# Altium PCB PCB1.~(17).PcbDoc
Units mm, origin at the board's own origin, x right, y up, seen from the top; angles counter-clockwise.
Board outline 145.29 x 144.91 mm, 2 copper layers (Top Layer, Bottom Layer); 48 components, 44 nets, 249 pads, 0 vias.
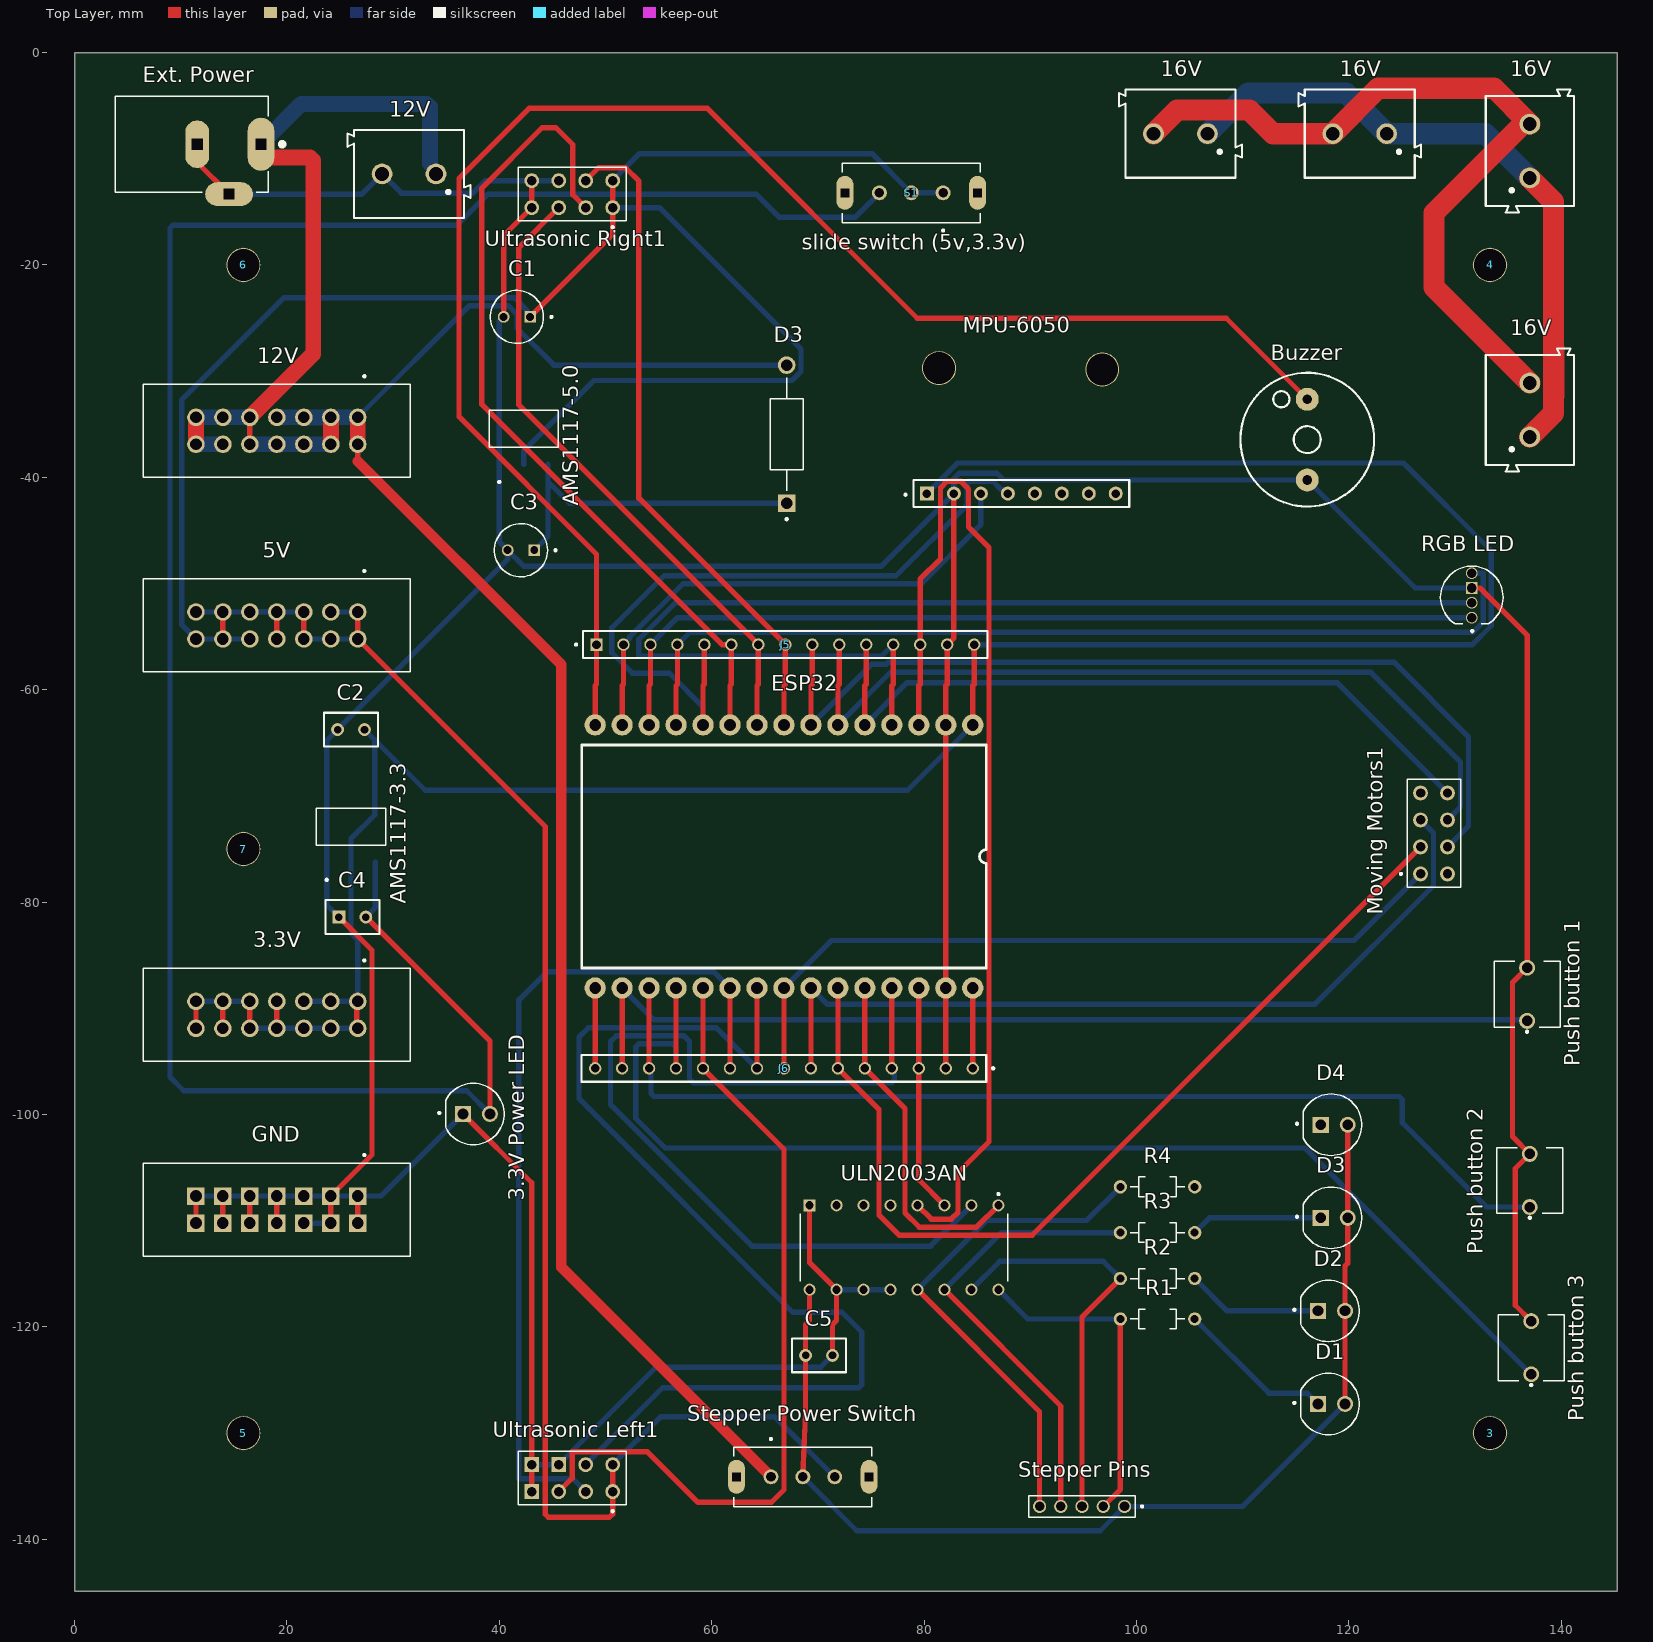
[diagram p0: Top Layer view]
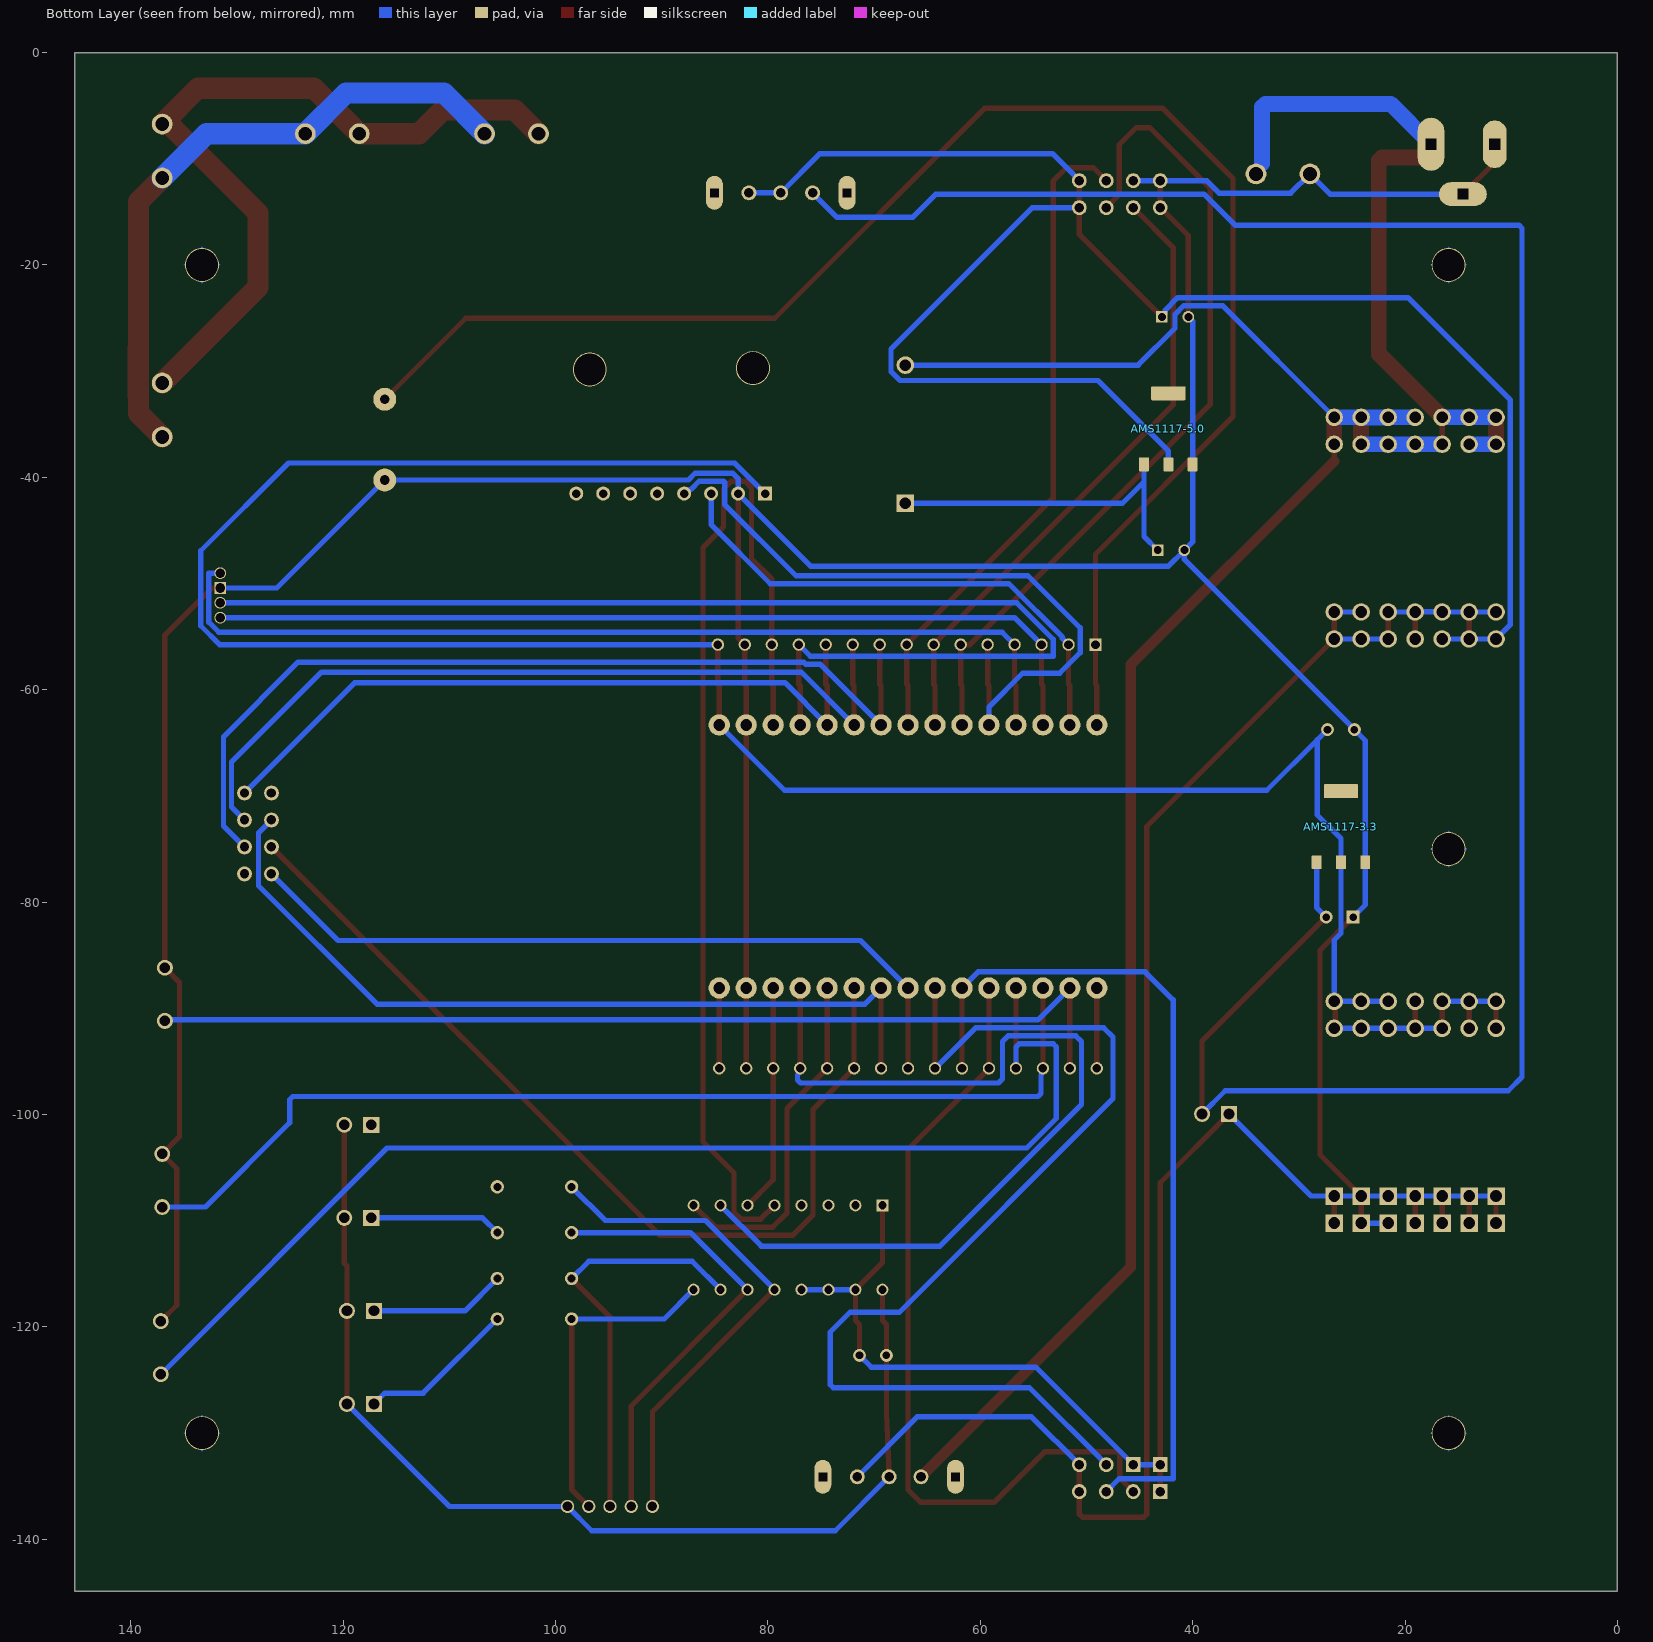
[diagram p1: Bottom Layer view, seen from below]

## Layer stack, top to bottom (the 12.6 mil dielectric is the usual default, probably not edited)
Top Solder: solder mask 0.0102, Solder Resist, Dk 3.5
Top Layer: signal copper 0.0356
Dielectric 1: dielectric 0.32, FR-4, Dk 4.8
Bottom Layer: signal copper 0.0356
Bottom Solder: solder mask 0.0102, Solder Resist, Dk 3.5

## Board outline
0,-144.907 145.288,-144.907 145.288,0 0,0

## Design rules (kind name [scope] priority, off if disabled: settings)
Clearance [All] p1: gap=0.254 ignorepadtopadclearanceinfootprint=FALSE except(0: Arc-Hole Track-Hole SMDPad-Hole THPad-Hole Via-Hole Fill-Hole Poly-Hole Region-Hole Text-Hole; 2: Arc-Poly Track-Poly SMDPad-Poly THPad-Poly)
PolygonConnect [All] p1: connectstyle=Relief reliefconductorwidth=0.254 reliefentries=4 polygonreliefangle="90 Angle" airgapwidth=0.254
RoutingVias [All] p1: holewidth=0.711 width=1.27 viastyle="Through Hole" minholewidth=0.711 minwidth=1.27 maxholewidth=0.711 maxwidth=1.27
SolderMaskExpansion [All] p1: expansion=0.102 istentingtop=FALSE
Width [All] p1: maxlimit=3 minlimit=0.254 preferedwidth=2
30 further rules are at their usual default settings.

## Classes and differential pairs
component class Sheet1: 3 3.3V "3.3V Power LED" 4 5 5V 6 7 12V 16V AMS1117-3.3 AMS1117-5.0 Buzzer C1 C2 C3 C4 C5 D1 D2 D3 ESP32 "Ext. Power" GND J5 J6 "Moving motors" "Moving Motors1" MPU-6050 "Push button 1" "Push button 2" "Push button 3" R1 R2 R3 R4 "RGB LED" S1 "Stepper Pins" "Stepper Power Switch" ULN2003AN "Ultrasonic Left1" "Ultrasonic Right1"

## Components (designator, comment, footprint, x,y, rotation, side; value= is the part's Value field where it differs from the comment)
3 "Mounting Hole" PCBComponent_1 133.288,-130 r90 top
3.3V "3.3v pin headers block" AMPHENOL_52601-S14-4LF#1 19.05,-90.616 r180 top
"3.3V Power LED" "LED 5mm" "LED 5mm" 37.846,-99.949 r0 top
4 "Mounting Hole" PCBComponent_1 133.288,-20 r90 top
5 "Mounting Hole" PCBComponent_1 15.9,-130 r90 top
5V "5v pin headers block" AMPHENOL_52601-S14-4LF#1 19.05,-53.949 r180 top
6 "Mounting Hole" PCBComponent_1 15.9,-20 r90 top
7 "Mounting Hole" PCBComponent_1 15.9,-75 r90 top
12V "12v pin headers block" AMPHENOL_52601-S14-4LF#1 19.05,-35.616 r180 top
12V "From Buck" 691213510002 31.496,-11.43 r180 top
16V "From Buck" 691213510002 137.033,-9.271 r90 top
16V "From Buck" 691213510002 137.033,-33.655 r90 top
16V "From Buck" 691213510002 121.02,-7.641 r180 top
16V "From Buck" 691213510002 104.14,-7.641 r180 top
AMS1117-3.3 "AMS1117-3.3" SOT229P700X180-4N 26.035,-72.898 r90 top
AMS1117-5.0 "AMS1117-5.0" SOT229P700X180-4N 42.291,-35.433 r90 top
Buzzer "WST-1205S" WST-1205S 116.078,-36.449 r90 top
C1 "CAP  33UF 50V RADIAL" "CAP  33UF 50V RADIAL" 41.656,-24.892 r180 top
C2 "Ceramic Capacitor 100nF" C320C#1 33.035,-56.754 r0 top
C3 "CAP  33UF 50V RADIAL" "CAP  33UF 50V RADIAL" 42.037,-46.863 r180 top
C4 "Ceramic Capacitor 100nF" C320C#2 33.162,-74.407 r0 top
C5 "Ceramic Capacitor 100nF" C320C#1 63.104,-129.682 r180 top
D1 "LED 5mm" "LED 5mm" 118.364,-127.254 r0 top
D2 "LED 5mm" "LED 5mm" 118.364,-118.491 r0 top
D3 "LED 5mm" "LED 5mm" 118.618,-109.728 r0 top
D3 "RL207" DIOAD1300W80L670D310 67.056,-35.941 r90 top
D4 "LED 5mm" "LED 5mm" 118.618,-100.965 r0 top
ESP32 "ESP32DEVKITV1" ESP32DEVKITV1 66.929,-75 r90 top
"Ext. Power" "DC Power Jack Female Socket" "DC Power Jack Female Socket" 17.557,-8.636 r180 top
GND "GND pin headers block" AMPHENOL_52601-S14-4LF#2 19.05,-108.949 r180 top
J5 "TS-115-T-A-1" SAMTEC_TS-115-T-A-1#1 66.929,-55.753 r0 top
J6 "TS-115-T-A-1" SAMTEC_TS-115-T-A-1#2 66.802,-95.649 r180 top
"Moving Motors1" "Pin header female block 8 pin" "Pin header female block 8 pin"#1 128.016,-73.533 r90 top (schematic designator "Moving motors1")
MPU-6050 "MPU-6050" MPU-6050 78.74,-43.053 r90 top
"Push button 1" "FSM8JRT" TE_FSM8JRT 136.779,-91.186 r90 top
"Push button 2" "FSM8JRT" TE_FSM8JRT 137.033,-108.712 r90 top
"Push button 3" "FSM8JRT" TE_FSM8JRT 137.16,-124.46 r90 top
R1 "Resistor" RESAD700W45L350D185 101.981,-119.253 r180 top
R2 "Resistor" RESAD700W45L350D185 101.981,-115.443 r180 top
R3 "Resistor" RESAD700W45L350D185 101.981,-111.125 r180 top
R4 "Resistor" RESAD700W45L350D185 101.981,-106.807 r180 top
"RGB LED" "common cathode" "LED RGB 5mm" 131.572,-51.308 r90 top
S1 "slide switch (5v,3.3v)" "Slide switch" 78.788,-13.208 r180 top
"Stepper Pins" "Pin hreader 5 pins" "Pin hreader 5 pins" 98.869,-136.906 r180 top
"Stepper Power Switch" "Slide switch" "Slide switch" 68.58,-134.112 r0 top
ULN2003AN "ULN2003AN" DIP794W45P254L1969H508Q16 78.105,-112.522 r270 top
"Ultrasonic Left1" "Pin header female block 8 pin" "Pin header female block 8 pin"#2 46.863,-134.239 r180 top
"Ultrasonic Right1" "Pin header female block 8 pin" "Pin header female block 8 pin"#1 46.863,-13.335 r180 top

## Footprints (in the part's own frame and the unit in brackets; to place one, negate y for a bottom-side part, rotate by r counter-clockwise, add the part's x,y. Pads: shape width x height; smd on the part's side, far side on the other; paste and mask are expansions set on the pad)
691213510002 [mm]
  round 1.95 hole 1.3: 1(-2.54,0) 2(2.54,0)
  silkscreen extent -5.78,-4.15 5.78,4.15, body extent -5.68,-3.94 5.68,4.16, height 10
AMPHENOL_52601-S14-4LF#1 [mm]
  round 1.65 hole 1.1: 1(-7.62,-1.27) 2(-7.62,1.27) 3(-5.08,-1.27) 4(-5.08,1.27) 5(-2.54,-1.27) 6(-2.54,1.27) 7(0,-1.27) 8(0,1.27) 9(2.54,-1.27) 10(2.54,1.27) 11(5.08,-1.27) 12(5.08,1.27) 13(7.62,-1.27) 14(7.62,1.27)
  silkscreen extent -12.57,-5.23 12.57,4.38, body extent -12.57,-4.38 12.57,4.38, height 9.53
AMPHENOL_52601-S14-4LF#2 [mm]
  rect 1.65x1.65 hole 1.1: 1(-7.62,-1.27) 2(-7.62,1.27) 3(-5.08,-1.27) 4(-5.08,1.27) 5(-2.54,-1.27) 6(-2.54,1.27) 7(0,-1.27) 8(0,1.27) 9(2.54,-1.27) 10(2.54,1.27) 11(5.08,-1.27) 12(5.08,1.27) 13(7.62,-1.27) 14(7.62,1.27)
  silkscreen extent -12.57,-5.23 12.57,4.38, body extent -12.57,-4.38 12.57,4.38, height 9.53
C320C#1 [mm]
  round 1.21 hole 0.71: 1(-8.27,-7) 2(-5.73,-7)
  silkscreen extent -9.54,-8.59 -4.46,-5.41, body extent -9.53,-8.57 -4.45,-5.4, height 7.1
C320C#2 [mm]
  rect 1.21x1.21 hole 0.71: 1(-8.27,-7)
  round 1.21 hole 0.71: 2(-5.73,-7)
  silkscreen extent -9.54,-8.59 -4.46,-5.41, body extent -9.53,-8.57 -4.45,-5.4, height 7.1
"CAP  33UF 50V RADIAL" [mm]
  round 1.1 hole 0.75: N(1.25,0)
  rect 1.1x1.1 hole 0.75: P(-1.25,0)
  silkscreen extent -3.35,-2.5 2.5,2.5, body extent -2.49,-2.5 2.5,2.5, height 11
"DC Power Jack Female Socket" [mm]
  oval 2.5x5 hole 1 square: 1(0,0)
  oval 2.25x4.5 hole 1 square: 2(6,0)
  oval 4.5x2.25 hole 1 square: 3(3,4.7)
  silkscreen extent -2.2,-4.5 13.7,4.5, body extent -0.7,-4.5 13.7,4.9, height 11
DIOAD1300W80L670D310 [mm]
  round 1.65 hole 1.1: A(6.5,0)
  rect 1.65x1.65 hole 1.1: C(-6.5,0)
  silkscreen extent -8.1,-1.55 5.32,1.55, body extent -6.9,-1.95 6.9,1.65, height 3.6
DIP794W45P254L1969H508Q16 [mm]
  round 1.13 hole 0.78: 1(-3.97,8.89) 2(-3.97,6.35) 3(-3.97,3.81) 4(-3.97,1.27) 5(-3.97,-1.27) 6(-3.97,-3.81) 7(-3.97,-6.35) 9(3.97,-8.89) 10(3.97,-6.35) 11(3.97,-3.81) 12(3.97,-1.27) 13(3.97,1.27) 14(3.97,3.81) 15(3.97,6.35) 16(3.97,8.89)
  rect 1.13x1.13 hole 0.78: 8(-3.97,-8.89)
  silkscreen extent -5.13,-9.77 3.18,9.77, body extent -3.95,-10.54 3.95,10.8, height 5.08
ESP32DEVKITV1 [mm]
  round 2 hole 1.1: 1(11.684,-17.653) 2(11.684,-15.113) 3(11.684,-12.573) 4(11.684,-10.033) 5(11.684,-7.493) 6(11.684,-4.953) 7(11.684,-2.413) 8(11.684,0.127) 9(11.684,2.667) 10(11.684,5.207) 11(11.684,7.747) 12(11.684,10.287) 13(11.684,12.827) 14(11.684,15.367) 15(11.684,17.907) 16(-13.086,17.907) 17(-13.086,15.367) 18(-13.086,12.827) 19(-13.086,10.287) 20(-13.086,7.747) 21(-13.086,5.207) 22(-13.086,2.667) 23(-13.086,0.127) 24(-13.086,-2.413) 25(-13.086,-4.953) 26(-13.086,-7.493) 27(-13.086,-10.033) 28(-13.086,-12.573) 29(-13.086,-15.113) 30(-13.086,-17.653)
  silkscreen extent -11.2,-18.92 9.79,19.18, body extent -15.13,-28.49 13.86,24.48, height 8.36
"LED 5mm" [mm]
  round 1.508 hole 1: A(1.27,0)
  rect 1.508x1.508 hole 1: C(-1.27,0)
  silkscreen extent -3.6,-2.9 2.6,2.9, body extent -2.88,-2.9 2.51,2.9, height 12.1
"LED RGB 5mm" [mm]
  round 1.1 hole 0.9: 1(-1.905,0) 2(-0.508,0) 4(2.286,0)
  rect 1.1x1.1 hole 0.9: 3(0.889,0)
  silkscreen extent -3.27,-2.95 2.95,2.95, body extent -2.47,-3.05 2.98,2.84, height 9.6
MPU-6050 [mil]
  rect 52x52 hole 32: 01(60,-60)
  round 52 hole 32: 02(60,-160) 03(60,-260) 04(60,-360) 05(60,-460) 06(60,-560) 07(60,-660) 08(60,-760)
  round 125.98 hole 118.11: ""(520,-710) ""(525,-105)
  silkscreen extent 10,-810 110,23, body extent 15,-811 615,-9, height 612
PCBComponent_1 [mm]
  round 3.2 hole 3: ""(0,0)
  Bottom Layer lines w0.15: 0,1.649 0,-1.651 ; -1.651,0 1.649,0
"Pin header female block 8 pin"#1 [mm]
  round 1.398 hole 0.89: 1(-3.81,1.27) 2(-1.27,1.27) 3(1.27,1.27) 4(3.81,1.27) 5(-3.81,-1.27) 6(-1.27,-1.27) 7(1.27,-1.27) 8(3.81,-1.27)
  silkscreen extent -5.08,-2.52 5.08,3.21, body extent -5.08,-2.51 5.08,2.51, height 6.22
"Pin header female block 8 pin"#2 [mm]
  round 1.398 hole 0.89: 1(-3.81,1.27) 2(-1.27,1.27) 3(1.27,1.27) 5(-3.81,-1.27) 6(-1.27,-1.27)
  rect 1.398x1.398 hole 0.89: 4(3.81,1.27) 7(1.27,-1.27) 8(3.81,-1.27)
  silkscreen extent -5.08,-2.52 5.08,3.21, body extent -5.08,-2.51 5.08,2.51, height 6.22
"Pin hreader 5 pins" [mm]
  round 1.25 hole 0.9: 1(0,0) 2(2,0) 3(4,0) 4(6,0) 5(8,0)
  silkscreen extent -1.75,-1 9,1, body extent -1,-1 9,1, height 5.65
RESAD700W45L350D185 [mm]
  round 1.258 hole 0.75: 1(-3.5,0) 2(3.5,0)
  silkscreen extent -2.55,-0.93 2.55,0.93, body extent -3.72,-1.05 3.72,0.8, height 1.85
SAMTEC_TS-115-T-A-1#1 [mil]
  rect 45.78x45.78 hole 32: 01(-700,0)
  round 45.78 hole 32: 02(-600,0) 03(-500,0) 04(-400,0) 05(-300,0) 06(-200,0) 07(-100,0) 08(0,0) 09(100,0) 10(200,0) 11(300,0) 12(400,0) 13(500,0) 14(600,0) 15(700,0)
  silkscreen extent -780,-50 750,50, body extent -754,-50 754,50, height 326
SAMTEC_TS-115-T-A-1#2 [mil]
  round 45.78 hole 32: 01(-700,0) 02(-600,0) 03(-500,0) 04(-400,0) 05(-300,0) 06(-200,0) 07(-100,0) 08(0,0) 09(100,0) 10(200,0) 11(300,0) 12(400,0) 13(500,0) 14(600,0) 15(700,0)
  silkscreen extent -780,-50 750,50, body extent -754,-50 754,50, height 326
"Slide switch" [mm]
  round 1.408 hole 0.9: 1(-3,0) 2(0,0) 3(3,0)
  oval 1.6x3.2 hole 0.8 square: SH1(-6.25,0) SH2(6.25,0)
  silkscreen extent -6.5,-2.8 6.5,3.66, body extent -6.5,-5.8 6.5,2.8, height 6
SOT229P700X180-4N [mm]
  rrect15% 1.31x0.93 smd far side: 1(-3.345,2.29) 2(-3.345,0) 3(-3.345,-2.29)
  rrect15% 1.31x3.24 smd far side: 4(3.345,0)
  silkscreen extent -5.1,-3.25 1.75,3.25, body extent -3.5,-3.25 3.5,3.25, height 1.8
TE_FSM8JRT [mil]
  round 59 hole 39: 1(0,0) 2(197,0)
  silkscreen extent -44,-122 220,122, body extent -22,-122 222,122, height 372
WST-1205S [mil]
  round 85 hole 36: NEG(-149.61,0) POS(149.61,0)
  silkscreen extent -248,-248 248,248, body extent -236,-236 236,236, height 394

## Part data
3.3V 5V 12V GND: library part 52601-S14-4LF, Package=None
"3.3V Power LED" D1 D2 D3 D4: "Red 623nm LED Indication - Discrete 1.9V Radial", Package=None
12V 16V 16V 16V 16V: library part "Terminal Block", "2 Position Wire to Board Terminal Block Horizontal with Board 0.200 (5.08mm) Through Hole", Package=None
AMS1117-3.3 AMS1117-5.0 J5 J6 "Moving Motors1" "Stepper Pins" "Stepper Power Switch" ULN2003AN "Ultrasonic Left1" "Ultrasonic Right1": Package=None
Buzzer: "BUZZER 2.3KHZ 4-6VDC", Package=None
C1 C3: "NHG-A", Package=None
C2 C4 C5: "0.1ÂµF Â±20% 50V Ceramic Capacitor Z5U Radial", Package="Radial KEMET"
D3: "Semiconductors and Actives, Power Diodes, Discretes (diodes, transistors, thyristors ...), Diodes", Package=None
"Ext. Power": "2.0 mm Center Pin, 2.5 A, Right Angle, Through Hole, Dc Power Jack Connector", Package=None
"Push button 1" "Push button 2" "Push button 3": "Tactile Switches PUSHBUTTON SWITCH TACT", Package=None
R1 R2 R3 R4: "CFR16 5% 10K", Package=None
"RGB LED": library part "LED RGB 5mm", Package=None
S1: library part "Slide switch", Package=None

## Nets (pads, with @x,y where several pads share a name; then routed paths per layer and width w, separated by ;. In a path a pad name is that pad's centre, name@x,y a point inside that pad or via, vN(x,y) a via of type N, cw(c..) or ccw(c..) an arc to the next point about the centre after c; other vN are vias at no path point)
3.3V: 3.3V.1 3.3V.2 3.3V.3 3.3V.4 3.3V.5 3.3V.6 3.3V.7 3.3V.8 3.3V.9 3.3V.10 3.3V.11 3.3V.12 3.3V.13 3.3V.14 AMS1117-3.3.2 C2.2 ESP32.1 J5.15 MPU-6050.01 | length 243
  Top Layer w0.5: 3.3V.14 3.3V.13 ; 3.3V.12 3.3V.11 ; 3.3V.10 3.3V.9 ; 3.3V.8 3.3V.7 ; 3.3V.2 26.585,-91.8 26.585,-89.431 3.3V.1 ; ESP32.1 84.582,-59.614 84.709,-59.487 J5.15
  Bottom Layer w0.5: 3.3V.13 3.3V.11 14.896,-89.346 14.91,-89.332 16.496,-89.332 3.3V.9 ; 3.3V.10 3.3V.8 3.3V.6 3.3V.4 3.3V.2 ; 3.3V.5 3.3V.3 3.3V.1 26.67,-83.566 26.035,-82.931 AMS1117-3.3.2 26.035,-74.016 28.27,-71.78 28.27,-64.719 ; C2.2 28.27,-64.719 ; MPU-6050.01 83.134,-38.659 125.146,-38.659 133.401,-46.914 133.401,-53.975 131.623,-55.753 J5.15 ; ESP32.1 78.429,-69.469 33.02,-69.469 28.27,-64.719
+5: 5V.1 5V.2 5V.3 5V.4 5V.5 5V.6 5V.7 5V.8 5V.9 5V.10 5V.11 5V.12 5V.13 5V.14 "Stepper Power Switch.3" "Ultrasonic Left1.1" "Ultrasonic Left1.5" "Ultrasonic Right1.1" "Ultrasonic Right1.5" AMS1117-5.0.2 C1.P S1.1 S1.2 | length 325.5
  Top Layer w0.5: 5V.12 5V.11 ; 5V.8 5V.7 ; 5V.6 5V.5 ; 5V.1 5V.2 44.323,-72.872 44.323,-137.629 44.616,-137.922 50.38,-137.922 50.673,-137.629 50.673,-135.509 50.673,-132.969 ; C1.P 50.673,-17.125 50.673,-14.605 50.673,-12.065
  Bottom Layer w0.5: 5V.13 5V.11 5V.9 16.535,-52.654 19.025,-52.654 5V.7 5V.5 ; 5V.10 5V.12 5V.14 10.084,-53.873 10.084,-32.715 19.715,-23.084 41.414,-23.084 42.606,-24.276 42.606,-24.592 C1.P ; 5V.6 5V.4 5V.2 ; 5V.3 5V.1 ; AMS1117-5.0.2 42.291,-37.516 48.92,-30.886 67.564,-30.886 68.402,-30.048 68.402,-27.915 55.093,-14.605 50.673,-14.605 ; 50.673,-132.969 55.169,-128.473 65.941,-128.473 71.58,-134.112 ; 50.673,-12.065 53.213,-9.525 75.105,-9.525 S1.2 S1.1
+12: 12V.1 12V.2@26.67,-36.886 12V.3 12V.4 12V.5 12V.6 12V.7 12V.8 12V.9 12V.10 12V.11 12V.12 12V.13 12V.14 "Ext. Power.1" "Stepper Power Switch.1" D3.A@67.056,-29.441 | length 253.8
  Top Layer w0.5: 12V.10 12V.9 ; 17.557,-9.881 17.557,-8.636 ; 22.186,-9.881 22.479,-10.173 ; 26.67,-38.481 26.67,-36.886 12V.1@26.67,-34.346
  Top Layer w1: 26.67,-38.481 45.847,-57.658 45.847,-114.379 65.58,-134.112
  Top Layer w1.5: 12V.14 12V.13 ; 12V.9 22.479,-28.377 22.479,-10.173 ; 17.557,-9.881 22.186,-9.881 ; 12V.4 12V.3 ; 12V.2@26.67,-36.886 12V.1@26.67,-34.346
  Bottom Layer w0.5: 14.905,-34.346 14.91,-34.341 ; 12V.9@16.505,-34.341 12V.9 ; 12V.5 12V.5@21.61,-34.366 ; 12V.3@24.11,-34.366 12V.3 ; 12V.1@26.67,-34.346 37.178,-23.838 40.843,-23.838 41.656,-24.651 41.656,-25.959 45.138,-29.441 D3.A@67.056,-29.441 ; 33.147,-4.826 33.452,-5.131 ; 33.452,-10.453 34.036,-11.038 12V.1@34.036,-11.43
  Bottom Layer w1.5: 12V.14 12V.12 ; 12V.13 12V.11 14.905,-34.346 ; 14.91,-34.341 12V.9@16.505,-34.341 ; 12V.10 12V.8 12V.6 12V.4 ; 17.557,-8.636 21.367,-4.826 33.147,-4.826 ; 12V.7 12V.5 ; 12V.5@21.61,-34.366 12V.3@24.11,-34.366 ; 12V.3 12V.1@26.67,-34.346 ; 33.452,-10.453 33.452,-5.131
GND: 12V.2@28.956,-11.43 "3.3V Power LED.C" "Ext. Power.2" "Ext. Power.3" "Push button 1.2" "Push button 2.2" "Push button 3.2" "RGB LED.3" "Ultrasonic Left1.4" "Ultrasonic Left1.7" "Ultrasonic Left1.8" "Ultrasonic Right1.4" "Ultrasonic Right1.7" "Ultrasonic Right1.8" AMS1117-3.3.1 AMS1117-5.0.1 Buzzer.NEG C1.N C2.1 C3.N C4.1 C5.1 ESP32.2 ESP32.29 GND.1 GND.2 GND.3 GND.4 GND.5 GND.6 GND.7 GND.8 GND.9 GND.10 GND.11 GND.12 GND.13 GND.14 J5.14 J6.02 MPU-6050.02 ULN2003AN.8 ULN2003AN.10 ULN2003AN.11 ULN2003AN.12 | length 512.9
  Top Layer w0.5: GND.14 GND.13 ; 11.557,-8.636 11.557,-10.336 14.557,-13.336 ; GND.12 GND.11 ; GND.10 GND.9 ; GND.8 GND.7 ; GND.4 GND.3 28.016,-103.793 28.016,-84.531 C4.1 ; GND.2 GND.1 ; 36.576,-99.949 43.053,-106.426 43.053,-132.969 43.053,-135.509 ; C1.N 40.406,-17.252 43.053,-14.605 43.053,-12.065 ; ULN2003AN.8 69.215,-113.952 ULN2003AN.10 71.755,-119.405 71.374,-119.786 C5.1 ; J6.02 ESP32.29 ESP32.2 82.042,-59.614 82.169,-59.487 J5.14 82.804,-55.118 MPU-6050.02 ; 131.572,-50.419 132.334,-50.419 136.779,-54.864 136.779,-86.182 135.407,-87.554 135.407,-102.083 137.033,-103.708 135.661,-105.08 135.661,-117.958 137.16,-119.456
  Bottom Layer w0.5: GND.13 11.43,-107.671 12.691,-107.671 12.7,-107.679 GND.11 13.97,-107.671 15.231,-107.671 15.24,-107.679 GND.9 16.519,-107.671 19.041,-107.671 GND.7 GND.5 GND.3 GND.1 28.846,-107.679 36.576,-99.949 ; 14.557,-13.336 27.05,-13.336 28.956,-11.43 30.77,-13.244 37.506,-13.244 38.684,-12.065 43.053,-12.065 45.593,-12.065 ; GND.6 21.607,-110.236 24.113,-110.236 GND.4 ; C4.1 23.745,-80.26 AMS1117-3.3.1 23.745,-64.774 C2.1 40.787,-47.732 C3.N ; C1.N 40.001,-25.297 AMS1117-5.0.1 40.001,-46.077 C3.N ; 43.053,-132.969 45.593,-132.969 54.762,-123.8 70.256,-123.8 C5.1 ; ULN2003AN.10 ULN2003AN.11 ULN2003AN.12 ; 131.572,-50.419 126.248,-50.419 Buzzer.NEG 87.48,-40.249 86.842,-39.611 83.32,-39.611 82.804,-40.127 MPU-6050.02 75.951,-48.382 42.306,-48.382 C3.N
"Net3.3V Power LED_A": "3.3V Power LED.A" AMS1117-3.3.3 C4.2 S1.3 | length 210.4
  Top Layer w0.5: C4.2 39.116,-93.091 39.116,-99.949
  Bottom Layer w0.5: C4.2 28.325,-80.514 AMS1117-3.3.3 ; 39.116,-99.949 36.932,-97.765 10.287,-97.765 8.989,-96.467 8.989,-16.549 9.282,-16.256 36.017,-16.256 38.938,-13.335 64.186,-13.335 66.37,-15.519 73.477,-15.519 S1.3
Net16V_1: 16V.1 | length 61.5
  Top Layer w2: 16V.1@137.033,-36.195 139.268,-33.96 139.268,-32.346 139.287,-32.328 139.287,-27.838 139.268,-27.82 139.268,-14.046 16V.1@137.033,-11.811
  Bottom Layer w2: 16V.1@106.68,-7.641 110.511,-3.81 119.73,-3.81 123.56,-7.641 132.863,-7.641 16V.1@137.033,-11.811
Net16V_2: 16V.2 | length 72.7
  Top Layer w2: 16V.2@101.6,-7.641 103.831,-5.41 110.617,-5.41 112.848,-7.641 118.48,-7.641 122.769,-3.353 133.655,-3.353 137.033,-6.731 136.398,-6.731 128.016,-15.113 128.016,-22.098 16V.2@137.033,-31.115
NetAMS1117-5.0_3: AMS1117-5.0.3 C3.P D3.C@67.056,-42.441 | length 31.9
  Bottom Layer w0.5: C3.P 44.581,-45.569 44.581,-40.413 ; AMS1117-5.0.3 44.581,-40.413 ; D3.C@67.056,-42.441 46.609,-42.441 44.581,-40.413
NetBuzzer_POS: Buzzer.POS ESP32.15 J5.01 | length 150.8
  Top Layer w0.5: ESP32.15 49.022,-59.614 49.149,-59.487 J5.01 49.149,-47.244 36.195,-34.29 36.195,-11.862 42.799,-5.258 59.588,-5.258 79.35,-25.019 108.448,-25.019 Buzzer.POS
NetC5_2: "Stepper Pins.1" "Stepper Power Switch.2" C5.2 D1.A D2.A D3.A@119.888,-109.728 D4.A ULN2003AN.9 | length 102.3
  Top Layer w0.5: 68.58,-134.112 68.834,-128.143 C5.2 68.834,-119.786 69.215,-119.405 ULN2003AN.9 ; D1.A D2.A 119.634,-114.249 119.888,-113.995 119.888,-109.728 D4.A
  Bottom Layer w0.5: 68.58,-134.112 73.66,-139.192 96.583,-139.192 98.869,-136.906 109.982,-136.906 D1.A
NetD1_C: D1.C R1.1 | length 14.9
  Bottom Layer w0.5: R1.1 112.466,-126.238 116.078,-126.238 D1.C
NetD2_C: D2.C R2.1 | length 12.9
  Bottom Layer w0.5: R2.1 108.529,-118.491 D2.C
NetD3_C: D3.C@117.348,-109.728 R3.1 | length 12.4
  Bottom Layer w0.5: R3.1 106.878,-109.728 D3.C@117.348,-109.728
NetD4_C: R4.1
NetESP32_3: ESP32.3 J5.13 ULN2003AN.4 | length 101.1
  Top Layer w0.5: ULN2003AN.4 80.678,-109.855 82.55,-109.855 83.185,-109.22 83.185,-105.486 86.106,-102.565 86.106,-46.609 84.176,-44.679 84.176,-41.097 83.439,-40.361 82.169,-40.361 81.534,-40.996 81.534,-47.676 79.629,-49.581 J5.13 79.629,-59.487 79.502,-59.614 ESP32.3
NetESP32_4: "RGB LED.2" ESP32.4 J5.12 | length 113.5
  Top Layer w0.5: ESP32.4 76.962,-59.614 77.089,-59.487 J5.12
  Bottom Layer w0.5: J5.12 75.997,-56.845 53.137,-56.845 53.137,-55.245 56.566,-51.816 131.572,-51.816
NetESP32_5: "Moving Motors1.8" ESP32.5 J5.11 | length 68.4
  Top Layer w0.5: ESP32.5 74.422,-59.614 74.549,-59.487 J5.11
  Bottom Layer w0.5: ESP32.5 78.404,-59.334 118.897,-59.334 129.286,-69.723
NetESP32_6: "Moving Motors1.7" ESP32.6 J5.10 | length 77.8
  Top Layer w0.5: ESP32.6 71.882,-59.614 72.009,-59.487 J5.10
  Bottom Layer w0.5: ESP32.6 76.854,-58.344 122.036,-58.344 130.505,-66.813 130.505,-71.044 129.286,-72.263
NetESP32_7: "Moving Motors1.6" ESP32.7 J5.09 | length 86.1
  Top Layer w0.5: ESP32.7 69.342,-59.614 69.469,-59.487 J5.09
  Bottom Layer w0.5: ESP32.7 75.051,-57.607 76.429,-57.607 76.632,-57.404 124.231,-57.404 131.267,-64.44 131.267,-72.822 129.286,-74.803
NetESP32_8: "Ultrasonic Right1.6" ESP32.8 J5.08 | length 63
  Top Layer w0.5: 48.133,-12.065 49.352,-10.846 51.892,-10.846 53.137,-12.09 53.137,-41.961 J5.08 66.929,-59.487 66.802,-59.614 ESP32.8
NetESP32_9: "Ultrasonic Right1.3" ESP32.9 J5.07 | length 59.7
  Top Layer w0.5: 45.593,-14.605 41.834,-18.364 41.834,-33.198 J5.07 64.389,-59.487 64.262,-59.614 ESP32.9
NetESP32_10: "Ultrasonic Right1.2" ESP32.10 J5.06 | length 78.9
  Top Layer w0.5: 48.133,-14.605 46.914,-13.386 46.914,-8.661 45.339,-7.087 44.018,-7.087 38.354,-12.751 38.354,-33.147 60.96,-55.753 J5.06 61.849,-59.487 61.722,-59.614 ESP32.10
NetESP32_11: ESP32.11 J5.05 MPU-6050.04 | length 67.1
  Top Layer w0.5: ESP32.11 59.182,-59.614 59.309,-59.487 J5.05
  Bottom Layer w0.5: ESP32.11 59.182,-61.62 56.007,-58.445 52.527,-58.445 50.597,-56.515 50.597,-54.167 55.499,-49.265 77.354,-49.265 84.074,-42.545 84.074,-40.466 84.176,-40.365 86.466,-40.365 87.249,-41.148 87.503,-41.148 MPU-6050.04
NetESP32_12: "RGB LED.4" ESP32.12 J5.04 | length 90
  Top Layer w0.5: ESP32.12 56.642,-59.614 56.769,-59.487 J5.04
  Bottom Layer w0.5: J5.04 57.937,-54.585 131.699,-54.585 132.639,-53.645 132.639,-49.022 131.572,-49.022
NetESP32_13: "RGB LED.1" ESP32.13 J5.03 | length 86
  Top Layer w0.5: ESP32.13 54.102,-59.614 54.229,-59.487 J5.03
  Bottom Layer w0.5: J5.03 56.769,-53.213 131.572,-53.213
NetESP32_14: ESP32.14 J5.02 MPU-6050.03 | length 48.9
  Top Layer w0.5: ESP32.14 51.562,-59.614 51.689,-59.487 J5.02
  Bottom Layer w0.5: J5.02 52.273,-55.169 52.273,-55.042 57.297,-50.019 79.775,-50.019 85.344,-44.45 MPU-6050.03
NetESP32_16: ESP32.16 J6.15 | length 7.6
  Top Layer w0.5: J6.15 ESP32.16
NetESP32_17: "Push button 1.1" ESP32.17 J6.14 | length 94.1
  Top Layer w0.5: J6.14 ESP32.17
  Bottom Layer w0.5: ESP32.17 54.559,-91.083 136.676,-91.083 136.779,-91.186
NetESP32_18: "Push button 2.1" ESP32.18 J6.13 | length 98.5
  Top Layer w0.5: J6.13 ESP32.18
  Bottom Layer w0.5: J6.13 54.229,-95.776 54.229,-96.221 54.281,-96.273 54.281,-98.005 54.574,-98.298 124.726,-98.298 125.019,-98.591 125.019,-100.762 132.969,-108.712 137.033,-108.712
NetESP32_19: "Push button 3.1" ESP32.19 J6.12 | length 114.7
  Top Layer w0.5: J6.12 ESP32.19
  Bottom Layer w0.5: J6.12 56.642,-93.638 56.349,-93.345 53.125,-93.345 52.832,-93.638 52.832,-100.355 55.626,-103.149 115.849,-103.149 137.16,-124.46
NetESP32_20: "Ultrasonic Left1.3" ESP32.20 J6.11 | length 77.1
  Top Layer w0.5: 45.593,-135.509 46.863,-134.239 46.863,-131.75 53.924,-131.75 58.699,-136.525 65.608,-136.525 66.802,-135.331 66.802,-103.269 J6.11 ESP32.20
NetESP32_21: "Ultrasonic Left1.2" ESP32.21 J6.10 | length 81.1
  Top Layer w0.5: J6.10 ESP32.21
  Bottom Layer w0.5: 48.133,-135.509 46.914,-134.29 41.834,-134.29 41.834,-89.205 44.475,-86.563 60.199,-86.563 ESP32.21
NetESP32_22: "Ultrasonic Left1.6" ESP32.22 J6.09 | length 101.9
  Top Layer w0.5: J6.09 ESP32.22
  Bottom Layer w0.5: 48.133,-132.969 55.372,-125.73 73.834,-125.73 74.127,-125.437 74.127,-120.482 72.263,-118.618 67.615,-118.618 47.498,-98.501 47.498,-92.71 48.371,-91.837 60.45,-91.837 J6.09
NetESP32_23: "Moving Motors1.1" ESP32.23 J6.08 | length 72
  Top Layer w0.5: J6.08 ESP32.23
  Bottom Layer w0.5: ESP32.23 71.271,-83.617 120.472,-83.617 126.746,-77.343
NetESP32_24: "Moving Motors1.3" ESP32.24 J6.07 | length 78.1
  Top Layer w0.5: J6.07 ESP32.24
  Bottom Layer w0.5: ESP32.24 70.867,-89.611 116.815,-89.611 127.965,-78.461 127.965,-73.482 126.746,-72.263
NetESP32_25: "Moving Motors1.2" ESP32.25 J6.06 | length 89.9
  Top Layer w0.5: ESP32.25 J6.06 75.743,-99.51 75.743,-109.474 77.632,-111.363 90.186,-111.363 126.746,-74.803
NetESP32_26: ESP32.26 J6.05 ULN2003AN.1 | length 32.9
  Top Layer w0.5: ESP32.26 J6.05 78.207,-99.434 78.207,-109.271 79.545,-110.609 84.938,-110.609 ULN2003AN.1
NetESP32_27: ESP32.27 J6.04 ULN2003AN.2 | length 86.8
  Top Layer w0.5: J6.04 ESP32.27
  Bottom Layer w0.5: J6.04 77.089,-95.776 77.089,-96.146 77.216,-96.273 77.216,-96.735 76.923,-97.028 58.293,-97.028 57.912,-96.647 57.912,-93.13 57.373,-92.591 51.009,-92.591 50.47,-93.13 50.47,-99.06 63.805,-112.395 80.612,-112.395 ULN2003AN.2
NetESP32_28: ESP32.28 J6.03 ULN2003AN.3 | length 21.5
  Top Layer w0.5: ESP32.28 J6.03 79.502,-106.139 ULN2003AN.3
NetESP32_30: ESP32.30 J6.01 | length 7.6
  Top Layer w0.5: J6.01 ESP32.30
NetR1_2: "Stepper Pins.2" R1.2 ULN2003AN.16 | length 31
  Top Layer w0.5: 96.869,-136.906 98.481,-135.294 R1.2
  Bottom Layer w0.5: ULN2003AN.16 89.756,-119.253 R1.2
NetR2_2: "Stepper Pins.3" R2.2 ULN2003AN.15 | length 38.8
  Top Layer w0.5: 94.869,-136.906 94.869,-119.055 R2.2
  Bottom Layer w0.5: ULN2003AN.15 87.13,-113.817 96.855,-113.817 R2.2
NetR3_2: "Stepper Pins.4" R3.2 ULN2003AN.14 | length 43.7
  Top Layer w0.5: ULN2003AN.14 92.869,-127.446 92.869,-136.906
  Bottom Layer w0.5: ULN2003AN.14 87.282,-111.125 R3.2
NetR4_2: "Stepper Pins.5" R4.2 ULN2003AN.13 | length 48.3
  Top Layer w0.5: ULN2003AN.13 90.869,-127.986 90.869,-136.906
  Bottom Layer w0.5: ULN2003AN.13 85.885,-109.982 95.306,-109.982 R4.2
pads on no net: 3. 4. 5. 6. 7. "Moving Motors1.4" "Moving Motors1.5" "Stepper Power Switch.SH1" "Stepper Power Switch.SH2" AMS1117-3.3.4 AMS1117-5.0.4 D4.C MPU-6050. MPU-6050.05 MPU-6050.06 MPU-6050.07 MPU-6050.08 S1.SH1 S1.SH2 ULN2003AN.5 ULN2003AN.6 ULN2003AN.7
